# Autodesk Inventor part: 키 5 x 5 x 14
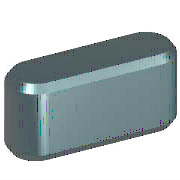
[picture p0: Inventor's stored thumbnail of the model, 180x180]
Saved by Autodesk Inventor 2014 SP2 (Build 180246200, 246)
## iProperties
IsCustomPart: 1
Created: 2012-02
Part Number: 키 5 x 5 x 14
Material: 강철, 연강
Description: 키 및 해당 키홈
Document SubType Name: Modeling
Standard: KS B 1311
Designer: mduedu
Standards Organization: KS
Language: ko-KR
Size Designation: 5 x 5 x 14
Categories: <MemberInstance><Categories><Category DisplayName="샤프트 부품" InternalName="7f7aeb1f-a693-4053-b835-cee3144e0d98" Mnemonic="SHFT"><Category DisplayName="키" Interna
Density: 1 g/cm^3
Appearance: 노란색
Author: mduedu
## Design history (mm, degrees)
workplane "Work Plane1"
workplane "Work Plane2"
sketch "스케치1"
  geometry: L1 (2.5, 2.5)-(11.5, 2.5); L2 (11.5, -2.5)-(2.5, -2.5); L3 (0, 9.4)-(0, -7.4) reference; L4 (-5, 0)-(30, 0) reference; L5 (14, 0)-(14, 7); A1 r 2.5 centre (2.5, 0) between (2.5, 2.5) and (2.5, -2.5); A2 r 2.5 centre (11.5, 0) between (11.5, -2.5) and (11.5, 2.5)
  constraints: 6 end point, 5 point on circle, 4 tangent, 3 point on line, 2 centre point, 1 horizontal, 1 parallel, 1 perpendicular
  dimensions: "d0" = 2.5 radius of A1 (= 0.5 x PB); "d13" = 2.5 radius of A2 (= 0.5 x PB); "d14" = 14 distance between parallel lines of L5 L3 (= NLG)
extrude "본체1" new body sketch "스케치1" taper "d3" = 0 deg; stored distance "d4" = 10
workplane "Work Plane3"
body "Solid1"
chamfer "모따기1" distance "d8" = 0.4 (= PHH); stored, may be unused: second distance "d9" = 0.4 (= PHH), angle "d15" = 45 deg
other parameters: "d1" = -3 (= -PNT), "d2" = 2 (= PH - PNT), "NLG" = 14 [user parameter; used in 3 equation terms], "PB" = 5 [user parameter; used in 2 equation terms], "PNT" = 3 [user parameter; used in 2 equation terms], "PH" = 5 [user parameter; used in 1 equation term], "PHH" = 0.4 [user parameter; used in 2 equation terms], "d10" = 0, "d16" = 0, "d17" = 0, "d18" = 0, "WDMIN" = 12 [user parameter], "PLB2" = 14 (= NLG) [user parameter], "WDMAX" = 17 [user parameter], "PLB1" = 14 (= NLG) [user parameter], "RR" = 0.16 [user parameter], "PUEB" = 2.3 [user parameter]
